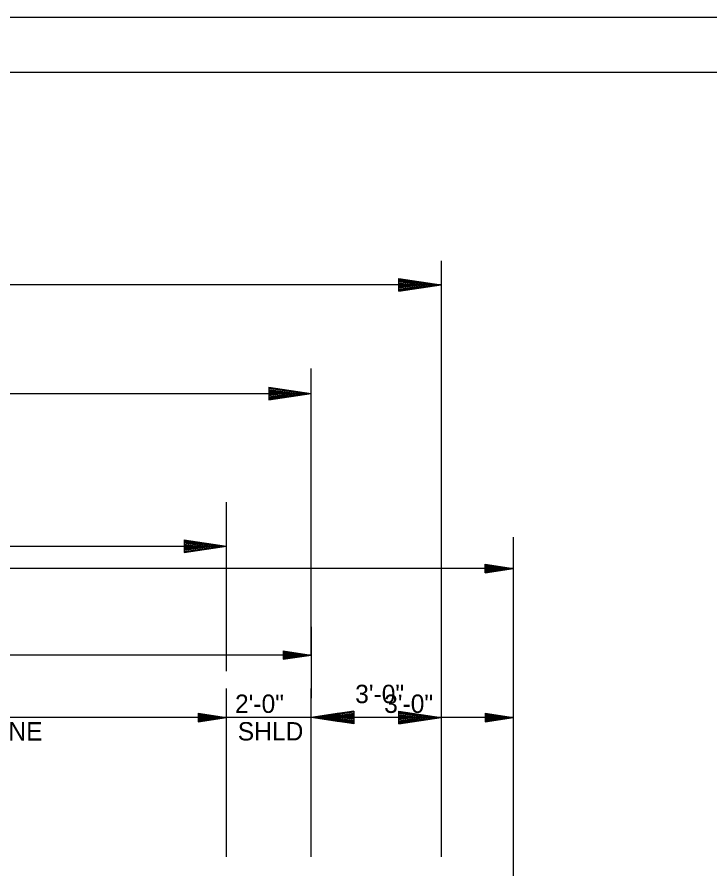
# Model space of a CAD drawing. Extents: x 1373719 to 1374161, y 379835 to 380167.
# Drawn here: x 1373974.45 to 1373998.95, y 379977.64 to 380007.76 of the extents above; entities that cross this region are included whole.
import ezdxf

# ---------------------------------------------------------------- set-up
doc = ezdxf.new("R2010")
doc.units = 0
for name, color, linetype in [('DATE', 7, 'Continuous'), ('GREEN_TXT', 7, 'Continuous'), ('R_NoPlot', 7, 'Continuous'), ('Text 1', 7, 'Continuous')]:
    doc.layers.add(name, color=color, linetype=linetype)

msp = doc.modelspace()

# ---------------------------------------------------------------- linework, layer by layer
at = {"layer": 'DATE'}
msp.add_line((1373885.973, 380005.815), (1374044.063, 380005.815), dxfattribs=at)
at = {"layer": 'GREEN_TXT'}
for p, q in [((1373992.005, 379975.434), (1373992.005, 379989.371)), ((1373991.005, 379988.411), (1373992.005, 379988.261)), ((1373991.005, 379988.111), (1373991.005, 379988.411)), ((1373991.005, 379988.386), (1373991.838, 379988.261)), ((1373992.005, 379988.261), (1373938.705, 379988.261)), ((1373991.005, 379988.36), (1373991.666, 379988.261)), ((1373991.005, 379988.335), (1373991.499, 379988.261)), ((1373991.005, 379988.31), (1373991.33, 379988.261)), ((1373991.005, 379988.284), (1373991.163, 379988.261)), ((1373991.005, 379988.111), (1373992.005, 379988.261)), ((1373991.005, 379988.212), (1373991.33, 379988.261)), ((1373991.005, 379988.161), (1373991.666, 379988.261)), ((1373991.005, 379988.136), (1373991.838, 379988.261)), ((1373991.005, 379988.186), (1373991.499, 379988.261)), ((1373991.005, 379988.237), (1373991.163, 379988.261)), ((1373984.855, 379986.2), (1373984.855, 379983.674)), ((1373984.855, 379985.2), (1373945.855, 379985.2)), ((1373983.855, 379985.35), (1373984.855, 379985.2)), ((1373983.855, 379985.35), (1373983.855, 379985.05)), ((1373983.855, 379985.325), (1373984.688, 379985.2)), ((1373983.855, 379985.3), (1373984.516, 379985.2)), ((1373983.855, 379985.275), (1373984.349, 379985.2)), ((1373983.855, 379985.249), (1373984.18, 379985.2)), ((1373983.855, 379985.224), (1373984.013, 379985.2)), ((1373983.855, 379985.05), (1373984.855, 379985.2)), ((1373983.855, 379985.151), (1373984.18, 379985.2)), ((1373983.855, 379985.101), (1373984.516, 379985.2)), ((1373983.855, 379985.075), (1373984.688, 379985.2)), ((1373983.855, 379985.126), (1373984.349, 379985.2)), ((1373983.855, 379985.177), (1373984.013, 379985.2)), ((1373981.855, 379978.068), (1373981.855, 379984.019)), ((1373984.855, 379978.068), (1373984.855, 379984.019)), ((1373981.855, 379982.992), (1373965.355, 379982.992)), ((1373980.855, 379983.142), (1373981.855, 379982.992)), ((1373980.855, 379983.142), (1373980.855, 379982.842)), ((1373980.855, 379983.117), (1373981.688, 379982.992)), ((1373980.855, 379983.091), (1373981.516, 379982.992)), ((1373980.855, 379983.066), (1373981.349, 379982.992)), ((1373980.855, 379983.04), (1373981.18, 379982.992)), ((1373980.855, 379983.015), (1373981.013, 379982.992)), ((1373980.855, 379982.842), (1373981.855, 379982.992)), ((1373980.855, 379982.943), (1373981.18, 379982.992)), ((1373980.855, 379982.892), (1373981.516, 379982.992)), ((1373980.855, 379982.867), (1373981.688, 379982.992)), ((1373980.855, 379982.917), (1373981.349, 379982.992)), ((1373980.855, 379982.968), (1373981.013, 379982.992)), ((1373984.855, 379982.992), (1373981.855, 379982.992)), ((1373985.855, 379983.142), (1373984.855, 379982.992)), ((1373992.005, 379982.992), (1373984.855, 379982.992)), ((1373985.855, 379982.842), (1373984.855, 379982.992)), ((1373985.855, 379983.117), (1373985.022, 379982.992)), ((1373985.855, 379982.867), (1373985.022, 379982.992)), ((1373985.855, 379983.091), (1373985.194, 379982.992)), ((1373985.855, 379982.892), (1373985.194, 379982.992)), ((1373985.855, 379983.066), (1373985.36, 379982.992)), ((1373985.855, 379982.917), (1373985.36, 379982.992)), ((1373985.855, 379983.04), (1373985.53, 379982.992)), ((1373985.855, 379982.943), (1373985.53, 379982.992)), ((1373985.855, 379983.015), (1373985.697, 379982.992)), ((1373985.855, 379982.968), (1373985.697, 379982.992)), ((1373985.855, 379983.142), (1373985.855, 379982.842)), ((1373991.005, 379983.142), (1373992.005, 379982.992)), ((1373991.005, 379983.142), (1373991.005, 379982.842)), ((1373991.005, 379983.117), (1373991.838, 379982.992)), ((1373991.005, 379983.091), (1373991.666, 379982.992)), ((1373991.005, 379983.066), (1373991.499, 379982.992)), ((1373991.005, 379983.04), (1373991.33, 379982.992)), ((1373991.005, 379983.015), (1373991.163, 379982.992)), ((1373991.005, 379982.842), (1373992.005, 379982.992)), ((1373991.005, 379982.943), (1373991.33, 379982.992)), ((1373991.005, 379982.892), (1373991.666, 379982.992)), ((1373991.005, 379982.867), (1373991.838, 379982.992)), ((1373991.005, 379982.917), (1373991.499, 379982.992)), ((1373991.005, 379982.968), (1373991.163, 379982.992))]:
    msp.add_line(p, q, dxfattribs=at)
at = {"layer": 'R_NoPlot'}
msp.add_lwpolyline([(1373879.769, 380007.762), (1374046.439, 380007.762), (1374046.439, 379901.093), (1373879.769, 379901.093)], close=True, dxfattribs=at)
at = {"layer": 'Text 1'}
for p, q in [((1373989.451, 379999.136), (1373989.451, 379978.068)), ((1373987.951, 379998.519), (1373989.451, 379998.294)), ((1373987.951, 379998.069), (1373987.951, 379998.519)), ((1373987.951, 379998.481), (1373989.201, 379998.294)), ((1373987.951, 379998.444), (1373988.943, 379998.294)), ((1373987.951, 379998.405), (1373988.692, 379998.294)), ((1373987.951, 379998.367), (1373988.439, 379998.294)), ((1373987.951, 379998.33), (1373988.188, 379998.294)), ((1373989.451, 379998.294), (1373965.355, 379998.294)), ((1373987.951, 379998.069), (1373989.451, 379998.294)), ((1373987.951, 379998.222), (1373988.439, 379998.294)), ((1373987.951, 379998.144), (1373988.943, 379998.294)), ((1373987.951, 379998.106), (1373989.201, 379998.294)), ((1373987.951, 379998.183), (1373988.692, 379998.294)), ((1373987.951, 379998.258), (1373988.188, 379998.294)), ((1373984.855, 379985.207), (1373984.855, 379995.335)), ((1373965.355, 379994.448), (1373984.855, 379994.448)), ((1373983.355, 379994.673), (1373984.855, 379994.448)), ((1373983.355, 379994.673), (1373983.355, 379994.223)), ((1373983.355, 379994.636), (1373984.604, 379994.448)), ((1373983.355, 379994.597), (1373984.346, 379994.448)), ((1373983.355, 379994.559), (1373984.096, 379994.448)), ((1373983.355, 379994.52), (1373983.842, 379994.448)), ((1373983.355, 379994.483), (1373983.592, 379994.448)), ((1373983.355, 379994.223), (1373984.855, 379994.448)), ((1373983.355, 379994.375), (1373983.842, 379994.448)), ((1373983.355, 379994.298), (1373984.346, 379994.448)), ((1373983.355, 379994.261), (1373984.604, 379994.448)), ((1373983.355, 379994.336), (1373984.096, 379994.448)), ((1373983.355, 379994.412), (1373983.592, 379994.448)), ((1373981.855, 379984.634), (1373981.855, 379990.608)), ((1373980.355, 379989.281), (1373981.855, 379989.056)), ((1373980.355, 379989.281), (1373980.355, 379988.831)), ((1373965.355, 379989.056), (1373981.855, 379989.056)), ((1373980.355, 379989.243), (1373981.604, 379989.056)), ((1373980.355, 379989.204), (1373981.346, 379989.056)), ((1373980.355, 379989.167), (1373981.096, 379989.056)), ((1373980.355, 379989.128), (1373980.842, 379989.056)), ((1373980.355, 379989.09), (1373980.592, 379989.056)), ((1373980.355, 379988.831), (1373981.855, 379989.056)), ((1373980.355, 379988.982), (1373980.842, 379989.056)), ((1373980.355, 379988.906), (1373981.346, 379989.056)), ((1373980.355, 379988.868), (1373981.604, 379989.056)), ((1373980.355, 379988.943), (1373981.096, 379989.056)), ((1373980.355, 379989.02), (1373980.592, 379989.056)), ((1373986.355, 379983.217), (1373984.855, 379982.992)), ((1373986.355, 379982.767), (1373984.855, 379982.992)), ((1373989.451, 379982.992), (1373984.855, 379982.992)), ((1373986.355, 379983.179), (1373985.105, 379982.992)), ((1373986.355, 379982.804), (1373985.105, 379982.992)), ((1373986.355, 379983.14), (1373985.363, 379982.992)), ((1373986.355, 379982.842), (1373985.363, 379982.992)), ((1373986.355, 379983.103), (1373985.612, 379982.992)), ((1373986.355, 379982.879), (1373985.612, 379982.992)), ((1373986.355, 379983.064), (1373985.867, 379982.992)), ((1373986.355, 379982.918), (1373985.867, 379982.992)), ((1373986.355, 379983.026), (1373986.118, 379982.992)), ((1373986.355, 379982.956), (1373986.118, 379982.992)), ((1373986.355, 379983.217), (1373986.355, 379982.767)), ((1373987.951, 379983.217), (1373989.451, 379982.992)), ((1373987.951, 379982.767), (1373987.951, 379983.217)), ((1373987.951, 379983.179), (1373989.201, 379982.992)), ((1373987.951, 379983.142), (1373988.943, 379982.992)), ((1373987.951, 379983.103), (1373988.692, 379982.992)), ((1373987.951, 379983.065), (1373988.439, 379982.992)), ((1373987.951, 379983.028), (1373988.188, 379982.992)), ((1373987.951, 379982.767), (1373989.451, 379982.992)), ((1373987.951, 379982.92), (1373988.439, 379982.992)), ((1373987.951, 379982.842), (1373988.943, 379982.992)), ((1373987.951, 379982.804), (1373989.201, 379982.992)), ((1373987.951, 379982.881), (1373988.692, 379982.992)), ((1373987.951, 379982.956), (1373988.188, 379982.992))]:
    msp.add_line(p, q, dxfattribs=at)

# ---------------------------------------------------------------- texts
at = {"layer": 'GREEN_TXT'}
for s, p in [('2\'-0"', (1373982.158, 379983.155)), ('3\'-0"', (1373987.431, 379983.155)), ('TRAVEL LANE', (1373969.461, 379982.179)), ('SHLD', (1373982.255, 379982.18))]:
    msp.add_text(s, height=0.65, dxfattribs=at).set_placement(p)
at = {"layer": 'Text 1'}
msp.add_text('3\'-0"', height=0.65, dxfattribs=at).set_placement((1373986.406, 379983.501))

doc.saveas('drawing.dxf')
